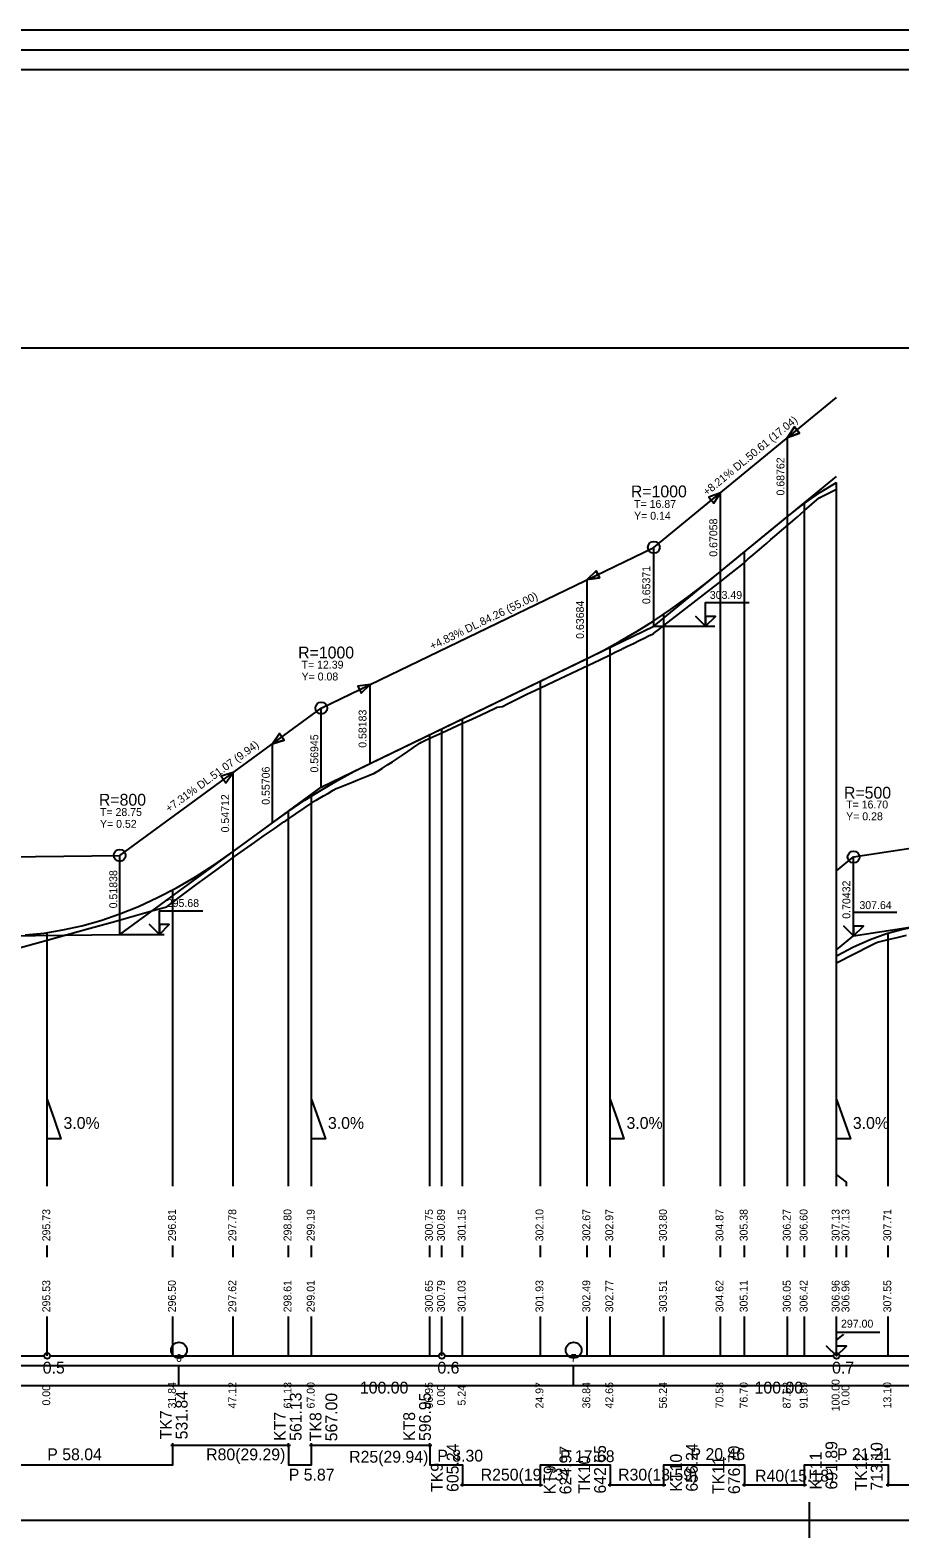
# Model space of a CAD drawing. Extents: x 999 to 1126, y 126 to 164.
# Drawn here: x 1063.75 to 1085.78, y 125.66 to 163.87 of the extents above; entities that cross this region are included whole.
import ezdxf

# ---------------------------------------------------------------- set-up
doc = ezdxf.new("R2010")
doc.units = 0
for name, color, linetype in [('KOTA', 7, 'Continuous'), ('NOVY_STAV', 7, 'Continuous'), ('NS_OBLOUK', 7, 'Continuous'), ('REZY_PO', 7, 'Continuous'), ('SESTAVY_REZU_PO', 7, 'Continuous'), ('SKLONOVE_POMERY', 7, 'Continuous'), ('SMEROVE_POMERY', 7, 'Continuous'), ('SMEROVE_POMERY_KOD', 7, 'Continuous'), ('SVK', 7, 'Continuous'), ('SVK_STAT', 7, 'Continuous'), ('TABULKY', 7, 'Continuous'), ('u_pricne_rezy', 7, 'Continuous'), ('x_formát_rám', 7, 'Continuous')]:
    doc.layers.add(name, color=color, linetype=linetype)

msp = doc.modelspace()

# ---------------------------------------------------------------- linework, layer by layer
at = {"layer": 'KOTA'}
for p, q in [((1079.549, 148.762), (1081.091, 148.762)), ((1066.016, 140.955), (1067.141, 140.955))]:
    msp.add_line(p, q, dxfattribs=at)
for points in [[(1080.861, 148.762), (1080.611, 149.012), (1080.861, 148.762), (1080.861, 149.362), (1081.961, 149.362)], [(1080.861, 149.012), (1080.861, 148.762), (1081.111, 149.012), (1080.861, 149.012)], [(1080.861, 148.762), (1081.111, 149.012), (1080.861, 149.012)], [(1080.861, 148.762), (1080.861, 148.762)], [(1067.02, 140.955), (1066.77, 141.205), (1067.02, 140.955), (1067.02, 141.555), (1068.12, 141.555)], [(1084.61, 140.916), (1084.36, 141.166), (1084.61, 140.916), (1084.61, 141.516), (1085.71, 141.516)], [(1067.02, 141.205), (1067.02, 140.955), (1067.27, 141.205), (1067.02, 141.205)], [(1067.02, 140.955), (1067.27, 141.205), (1067.02, 141.205)], [(1084.61, 141.166), (1084.61, 140.916), (1084.86, 141.166), (1084.61, 141.166)], [(1084.61, 140.916), (1084.86, 141.166), (1084.61, 141.166)], [(1067.02, 140.955), (1067.02, 140.955)], [(1084.61, 140.916), (1084.61, 140.916)], [(1084.178, 130.273), (1083.928, 130.523), (1084.178, 130.273), (1084.178, 130.873), (1085.278, 130.873)], [(1084.178, 130.273), (1084.428, 130.523), (1084.178, 130.523)]]:
    msp.add_lwpolyline(points, dxfattribs=at)
at = {"layer": 'NOVY_STAV'}
for points in [[(1079.549, 150.762), (1084.178, 154.561)], [(1054.178, 140.22), (1055.344, 140.824), (1066.016, 140.955), (1071.123, 144.689), (1079.549, 148.762), (1084.178, 152.561)], [(1063.62, 140.94), (1064.099, 140.989), (1064.578, 141.067), (1065.057, 141.173), (1065.536, 141.308), (1066.016, 141.472), (1066.495, 141.664), (1066.974, 141.885), (1067.453, 142.135), (1067.932, 142.414), (1068.411, 142.721), (1068.89, 143.057), (1069.884, 143.784), (1070.297, 144.077), (1070.71, 144.353), (1071.123, 144.612), (1071.536, 144.854), (1071.948, 145.08), (1072.361, 145.288), (1077.862, 147.946), (1078.283, 148.159), (1078.705, 148.39), (1079.127, 148.638), (1079.549, 148.904), (1079.971, 149.188), (1080.393, 149.49), (1080.814, 149.809), (1081.236, 150.147), (1082.94, 151.545), (1083.358, 151.871), (1083.775, 152.161), (1084.178, 152.408)], [(1071.123, 146.689), (1079.549, 150.762)], [(1079.549, 148.762), (1079.549, 150.762)], [(1066.016, 142.955), (1071.123, 146.689)], [(1071.123, 144.689), (1071.123, 146.689)], [(1084.178, 140.561), (1084.61, 140.916), (1091.178, 141.92), (1100.556, 145.632)], [(1084.178, 140.408), (1084.193, 140.417), (1084.61, 140.637), (1085.027, 140.823), (1085.445, 140.974), (1085.862, 141.09), (1086.28, 141.171), (1089.356, 141.642), (1089.812, 141.718), (1090.267, 141.809), (1090.723, 141.913), (1091.178, 142.031), (1091.633, 142.163), (1092.089, 142.309), (1092.544, 142.468), (1093, 142.641), (1100.556, 145.632)], [(1084.61, 142.916), (1091.178, 143.92)], [(1055.344, 142.824), (1066.016, 142.955)], [(1066.016, 140.955), (1066.016, 142.955)], [(1084.178, 142.561), (1084.61, 142.916)], [(1084.61, 140.916), (1084.61, 142.916)]]:
    msp.add_lwpolyline(points, dxfattribs=at)
for centre in [(1079.549, 150.762), (1071.123, 146.689), (1066.016, 142.955), (1084.61, 142.916)]:
    msp.add_circle(centre, 0.15, dxfattribs=at)
at = {"layer": 'NS_OBLOUK'}
for points in [[(1082.94, 153.545), (1083.236, 153.659), (1083.109, 153.813), (1082.94, 153.545)], [(1082.94, 151.545), (1082.94, 153.545)], [(1081.068, 151.879), (1081.236, 152.147), (1080.941, 152.034), (1081.068, 151.879)], [(1081.236, 150.147), (1081.236, 152.147)], [(1077.862, 149.946), (1078.175, 149.987), (1078.088, 150.167), (1077.862, 149.946)], [(1077.862, 147.946), (1077.862, 149.946)], [(1072.135, 147.067), (1072.361, 147.288), (1072.048, 147.247), (1072.135, 147.067)], [(1072.361, 145.288), (1072.361, 147.288)], [(1069.884, 145.784), (1070.185, 145.88), (1070.067, 146.041), (1069.884, 145.784)], [(1069.884, 143.784), (1069.884, 145.784)], [(1068.707, 144.799), (1068.891, 145.057), (1068.589, 144.961), (1068.707, 144.799)], [(1068.891, 143.057), (1068.891, 145.057)]]:
    msp.add_lwpolyline(points, dxfattribs=at)
for points in [[(1082.94, 153.545), (1083.109, 153.813), (1083.236, 153.659)], [(1081.236, 152.147), (1080.941, 152.034), (1081.068, 151.879)], [(1077.862, 149.946), (1078.088, 150.167), (1078.175, 149.987)], [(1072.361, 147.288), (1072.048, 147.247), (1072.135, 147.067)], [(1069.884, 145.784), (1070.067, 146.041), (1070.185, 145.88)], [(1068.891, 145.057), (1068.589, 144.961), (1068.707, 144.799)]]:
    msp.add_lwpolyline(points, close=True, dxfattribs=at)
at = {"layer": 'REZY_PO'}
for points in [[(1063.354, 140.576), (1064.178, 140.806), (1065.178, 141.086), (1065.915, 141.292), (1066.178, 141.366), (1066.885, 141.564), (1067.178, 141.645), (1067.208, 141.654), (1067.362, 141.769), (1067.362, 141.769), (1067.362, 141.769), (1067.566, 141.921), (1067.635, 141.972), (1067.77, 142.073), (1067.974, 142.224), (1068.178, 142.375), (1068.428, 142.559), (1068.678, 142.742), (1068.928, 142.924), (1069.178, 143.104), (1069.428, 143.283), (1069.469, 143.312), (1069.678, 143.459), (1069.928, 143.633), (1070.178, 143.804), (1070.235, 143.843), (1070.291, 143.881), (1070.291, 143.881), (1070.291, 143.881), (1070.878, 144.28), (1070.878, 144.28), (1070.878, 144.28), (1070.978, 144.347), (1070.994, 144.357), (1071.078, 144.405), (1071.178, 144.463), (1071.303, 144.535), (1071.428, 144.609), (1071.5, 144.651), (1071.553, 144.672), (1071.678, 144.723), (1071.803, 144.773), (1071.928, 144.824), (1072.053, 144.875), (1072.178, 144.925), (1072.303, 144.975), (1072.404, 145.015), (1072.428, 145.025), (1072.451, 145.034), (1072.539, 145.084), (1072.553, 145.092), (1072.678, 145.17), (1072.803, 145.249), (1072.928, 145.331), (1073.053, 145.413), (1073.178, 145.497), (1073.317, 145.592), (1073.456, 145.687), (1073.595, 145.783), (1073.622, 145.802), (1073.661, 145.826), (1073.734, 145.862), (1073.873, 145.927), (1073.873, 145.927), (1073.873, 145.927), (1074.178, 146.066), (1074.702, 146.304), (1074.94, 146.412), (1075.178, 146.522), (1075.511, 146.678), (1075.58, 146.711), (1075.711, 146.726), (1075.845, 146.793), (1076.178, 146.962), (1076.351, 147.05), (1076.426, 147.086), (1076.675, 147.203), (1077.178, 147.441), (1078.178, 147.915), (1078.443, 148.04), (1078.59, 148.111), (1078.737, 148.184), (1078.767, 148.199), (1078.884, 148.254), (1079.031, 148.325), (1079.178, 148.398), (1079.303, 148.462), (1079.428, 148.526), (1079.43, 148.527), (1079.538, 148.573), (1079.553, 148.584), (1079.678, 148.682), (1079.802, 148.779), (1080.178, 149.071), (1081.178, 149.848), (1081.508, 150.105), (1081.817, 150.35), (1081.848, 150.38), (1081.848, 150.38), (1081.848, 150.38), (1081.939, 150.468), (1082.013, 150.53), (1082.178, 150.669), (1082.345, 150.81), (1082.405, 150.862), (1082.511, 150.959), (1082.664, 151.084), (1082.678, 151.096), (1082.845, 151.24), (1083.011, 151.385), (1083.178, 151.53), (1083.272, 151.612), (1083.367, 151.694), (1083.736, 152.014), (1084.178, 152.237), (1084.178, 152.237)], [(1084.178, 140.237), (1085.059, 140.681), (1085.178, 140.738), (1085.216, 140.756), (1085.488, 140.823), (1085.718, 140.879), (1085.948, 140.936)]]:
    msp.add_lwpolyline(points, dxfattribs=at)
at = {"layer": 'SESTAVY_REZU_PO'}
for points in [[(1054.253, 130.273), (1064.103, 130.273)], [(1064.253, 130.273), (1074.103, 130.273)], [(1074.253, 130.273), (1084.103, 130.273)], [(1084.253, 130.273), (1094.103, 130.273)]]:
    msp.add_lwpolyline(points, dxfattribs=at)
for centre in [(1064.178, 130.273), (1074.178, 130.273), (1084.178, 130.273)]:
    msp.add_circle(centre, 0.075, dxfattribs=at)
at = {"layer": 'SKLONOVE_POMERY'}
for points in [[(1064.178, 135.773), (1064.178, 136.773), (1064.178, 136.773), (1064.353, 136.273), (1064.528, 135.773), (1064.178, 135.773)], [(1070.878, 135.773), (1070.878, 136.773), (1070.878, 136.773), (1071.053, 136.273), (1071.228, 135.773), (1070.878, 135.773)], [(1078.443, 135.773), (1078.443, 136.773), (1078.443, 136.773), (1078.618, 136.273), (1078.793, 135.773), (1078.443, 135.773)], [(1084.178, 135.773), (1084.178, 136.773), (1084.178, 136.773), (1084.353, 136.273), (1084.528, 135.773), (1084.178, 135.773)]]:
    msp.add_lwpolyline(points, dxfattribs=at)
at = {"layer": 'SMEROVE_POMERY'}
msp.add_lwpolyline([(1061.558, 127.51), (1067.362, 127.51), (1067.362, 128.01), (1070.291, 128.01), (1070.291, 127.51), (1070.878, 127.51), (1070.878, 128.01), (1073.873, 128.01), (1073.873, 127.51), (1074.702, 127.51), (1074.702, 127.01), (1076.675, 127.01), (1076.675, 127.51), (1078.443, 127.51), (1078.443, 127.01), (1079.802, 127.01), (1079.802, 127.51), (1081.848, 127.51), (1081.848, 127.01), (1083.367, 127.01), (1083.367, 127.51), (1085.488, 127.51), (1085.488, 127.01), (1087.25, 127.01)], dxfattribs=at)
at = {"layer": 'SMEROVE_POMERY_KOD'}
for points in [[(1067.312, 128.01), (1067.412, 128.01)], [(1067.362, 127.96), (1067.362, 128.06)], [(1070.241, 128.01), (1070.341, 128.01)], [(1070.291, 127.96), (1070.291, 128.06)], [(1070.828, 128.01), (1070.928, 128.01)], [(1070.878, 127.96), (1070.878, 128.06)], [(1073.823, 128.01), (1073.923, 128.01)], [(1073.873, 127.96), (1073.873, 128.06)], [(1074.652, 127.01), (1074.752, 127.01)], [(1074.702, 126.96), (1074.702, 127.06)], [(1076.625, 127.01), (1076.725, 127.01)], [(1076.675, 126.96), (1076.675, 127.06)], [(1078.393, 127.01), (1078.493, 127.01)], [(1078.443, 126.96), (1078.443, 127.06)], [(1079.752, 127.01), (1079.852, 127.01)], [(1079.802, 126.96), (1079.802, 127.06)], [(1081.798, 127.01), (1081.898, 127.01)], [(1081.848, 126.96), (1081.848, 127.06)], [(1083.317, 127.01), (1083.417, 127.01)], [(1083.367, 126.96), (1083.367, 127.06)], [(1085.438, 127.01), (1085.538, 127.01)], [(1085.488, 126.96), (1085.488, 127.06)]]:
    msp.add_lwpolyline(points, dxfattribs=at)
at = {"layer": 'SVK'}
for points in [[(1084.178, 134.573), (1084.178, 152.408)], [(1084.178, 132.773), (1084.178, 133.073)], [(1084.178, 130.273), (1084.178, 131.273)]]:
    msp.add_lwpolyline(points, dxfattribs=at)
at = {"layer": 'SVK_STAT'}
for points in [[(1083.367, 134.573), (1083.367, 151.877)], [(1082.94, 134.573), (1082.94, 151.545)], [(1081.848, 134.573), (1081.848, 150.649)], [(1081.236, 134.573), (1081.236, 150.147)], [(1079.802, 134.573), (1079.802, 149.075)], [(1078.443, 134.573), (1078.443, 148.246)], [(1077.862, 134.573), (1077.862, 147.946)], [(1076.675, 134.573), (1076.675, 147.373)], [(1074.702, 134.573), (1074.702, 146.419)], [(1073.873, 134.573), (1073.873, 146.018)], [(1074.178, 134.573), (1074.178, 146.166)], [(1070.878, 134.573), (1070.878, 144.459)], [(1070.291, 134.573), (1070.291, 144.073)], [(1068.891, 134.573), (1068.89, 143.057)], [(1084.428, 134.573), (1084.428, 134.673), (1084.178, 134.873), (1084.178, 142.408)], [(1067.362, 134.573), (1067.362, 142.088)], [(1064.178, 134.573), (1064.178, 141.002)], [(1085.488, 134.573), (1085.488, 140.986)], [(1064.178, 132.773), (1064.178, 133.073)], [(1067.362, 132.773), (1067.362, 133.073)], [(1068.891, 132.773), (1068.891, 133.073)], [(1070.291, 132.773), (1070.291, 133.073)], [(1070.878, 132.773), (1070.878, 133.073)], [(1073.873, 132.773), (1073.873, 133.073)], [(1074.178, 132.773), (1074.178, 133.073)], [(1074.702, 132.773), (1074.702, 133.073)], [(1076.675, 132.773), (1076.675, 133.073)], [(1077.862, 132.773), (1077.862, 133.073)], [(1078.443, 132.773), (1078.443, 133.073)], [(1079.802, 132.773), (1079.802, 133.073)], [(1081.236, 132.773), (1081.236, 133.073)], [(1081.848, 132.773), (1081.848, 133.073)], [(1082.94, 132.773), (1082.94, 133.073)], [(1083.367, 132.773), (1083.367, 133.073)], [(1084.428, 132.773), (1084.428, 133.073)], [(1085.488, 132.773), (1085.488, 133.073)], [(1064.178, 130.273), (1064.178, 131.273)], [(1067.362, 130.273), (1067.362, 131.273)], [(1068.891, 130.273), (1068.891, 131.273)], [(1070.291, 130.273), (1070.291, 131.273)], [(1070.878, 130.273), (1070.878, 131.273)], [(1073.873, 130.273), (1073.873, 131.273)], [(1074.178, 130.273), (1074.178, 131.273)], [(1074.702, 130.273), (1074.702, 131.273)], [(1076.675, 130.273), (1076.675, 131.273)], [(1077.862, 130.273), (1077.862, 131.273)], [(1078.443, 130.273), (1078.443, 131.273)], [(1079.802, 130.273), (1079.802, 131.273)], [(1081.236, 130.273), (1081.236, 131.273)], [(1081.848, 130.273), (1081.848, 131.273)], [(1082.94, 130.273), (1082.94, 131.273)], [(1083.367, 130.273), (1083.367, 131.273)], [(1085.488, 130.273), (1085.488, 131.273)], [(1084.178, 130.273), (1084.178, 130.673), (1084.353, 130.818), (1084.353, 130.818)]]:
    msp.add_lwpolyline(points, dxfattribs=at)
at = {"layer": 'TABULKY'}
for points in [[(1014.178, 162.868), (1100.556, 162.868), (1100.556, 163.868), (1014.178, 163.868), (1014.178, 162.868)], [(1014.178, 163.368), (1100.556, 163.368)]]:
    msp.add_lwpolyline(points, dxfattribs=at)
at = {"layer": 'u_pricne_rezy'}
for points in [[(1017.517, 129.52), (1103.895, 129.52), (1103.895, 130.02), (1017.517, 130.02), (1017.517, 129.52)], [(1067.517, 129.52), (1067.517, 130.02)], [(1077.517, 129.52), (1077.517, 130.02)]]:
    msp.add_lwpolyline(points, dxfattribs=at)
for centre in [(1067.517, 130.42), (1077.517, 130.42)]:
    msp.add_circle(centre, 0.2, dxfattribs=at)
at = {"layer": 'x_formát_rám'}
msp.add_line((1083.491, 125.663), (1083.491, 126.563), dxfattribs=at)
msp.add_lwpolyline([(999.491, 126.113), (1125.491, 126.113), (1125.491, 155.813), (999.491, 155.813)], close=True, dxfattribs=at)

# ---------------------------------------------------------------- texts
at = {"layer": 'KOTA'}
for s, p in [('303.49', (1080.968, 149.456)), ('295.68', (1067.208, 141.649)), ('307.64', (1084.758, 141.596)), ('297.00', (1084.292, 130.99))]:
    msp.add_text(s, height=0.2, dxfattribs=at).set_placement(p)
at = {"layer": 'NOVY_STAV'}
for s, rotation, p in [('+8.21% DL.50.61 (17.04)', 39.3799, (1080.894, 152.056)), (' 0.65371', 90, (1079.459, 149.251)), ('+4.83% DL.84.26 (55.00)', 25.797, (1073.933, 148.157)), (' 0.56945', 90, (1071.047, 144.982)), ('+7.31% DL.51.07 (9.94)', 36.1691, (1067.266, 144.037)), (' 0.51838', 90, (1065.953, 141.54)), (' 0.70432', 90, (1084.527, 141.277))]:
    msp.add_text(s, height=0.2, rotation=rotation, dxfattribs=at).set_placement(p)
at = {"layer": 'NS_OBLOUK'}
for s, p in [(' 0.68762', (1082.858, 152.001)), (' 0.67058', (1081.157, 150.45)), (' 0.63684', (1077.779, 148.368)), (' 0.58183', (1072.268, 145.608)), (' 0.55706', (1069.816, 144.165)), (' 0.54712', (1068.787, 143.465))]:
    msp.add_text(s, height=0.2, rotation=90, dxfattribs=at).set_placement(p)
for s, height, p in [('R=1000', 0.3, (1078.968, 152.029)), ('T= 16.87', 0.2, (1079.049, 151.762)), ('Y= 0.14', 0.2, (1079.049, 151.462)), ('R=1000', 0.3, (1070.538, 147.947)), ('T= 12.39', 0.2, (1070.623, 147.689)), ('Y= 0.08', 0.2, (1070.623, 147.389)), ('R=800', 0.3, (1065.489, 144.216)), ('R=500', 0.3, (1084.367, 144.394)), ('T= 28.75', 0.2, (1065.516, 143.955)), ('Y= 0.28', 0.2, (1084.422, 143.846)), ('T= 16.70', 0.2, (1084.422, 144.146)), ('Y= 0.52', 0.2, (1065.516, 143.655))]:
    msp.add_text(s, height=height, dxfattribs=at).set_placement(p)
at = {"layer": 'SESTAVY_REZU_PO'}
for s, p in [('0.5', (1064.066, 129.825)), ('0.6', (1074.066, 129.825)), ('0.7', (1084.066, 129.825))]:
    msp.add_text(s, height=0.3, dxfattribs=at).set_placement(p)
at = {"layer": 'SKLONOVE_POMERY'}
for p in [(1064.592, 136.026), (1071.292, 136.026), (1078.857, 136.026), (1084.592, 136.026)]:
    msp.add_text('3.0%', height=0.3, dxfattribs=at).set_placement(p)
at = {"layer": 'SMEROVE_POMERY'}
for s, p in [('P 58.04', (1064.181, 127.629)), ('R80(29.29)', (1068.206, 127.627)), ('R25(29.94)', (1071.829, 127.567)), ('P 8.30', (1074.063, 127.595)), ('P 17.68', (1077.171, 127.581)), ('P 20.46', (1080.478, 127.635)), ('P 21.21', (1084.188, 127.635)), ('P 5.87', (1070.299, 127.114)), ('R250(19.73)', (1075.162, 127.115)), ('R30(13.59)', (1078.644, 127.115)), ('R40(15.18)', (1082.115, 127.088))]:
    msp.add_text(s, height=0.3, dxfattribs=at).set_placement(p)
at = {"layer": 'SMEROVE_POMERY_KOD'}
for s, p in [('531.84', (1067.735, 128.158)), ('561.13', (1070.623, 128.12)), ('567.00', (1071.528, 128.11)), ('596.95', (1073.9, 128.117)), ('TK7', (1067.335, 128.158)), ('KT7', (1070.223, 128.12)), ('TK8', (1071.128, 128.11)), ('KT8', (1073.5, 128.117)), ('605.24', (1074.601, 126.826)), ('642.65', (1078.335, 126.785)), ('656.24', (1080.662, 126.833)), ('691.89', (1084.199, 126.887)), ('713.10', (1085.346, 126.86)), ('624.97', (1077.46, 126.765)), ('TK10', (1077.935, 126.785)), ('KT10', (1080.262, 126.833)), ('TK11', (1081.333, 126.772)), ('676.70', (1081.733, 126.772)), ('KT11', (1083.799, 126.887)), ('TK12', (1084.946, 126.86)), ('TK9', (1074.201, 126.826)), ('KT9', (1077.06, 126.765))]:
    msp.add_text(s, height=0.3, rotation=90, dxfattribs=at).set_placement(p)
at = {"layer": 'SVK'}
for s, p in [(' 307.13', (1084.255, 133.103)), (' 306.96', (1084.255, 131.303)), ('100.00', (1084.255, 128.867))]:
    msp.add_text(s, height=0.2, rotation=90, dxfattribs=at).set_placement(p)
at = {"layer": 'SVK_STAT'}
for s, p in [(' 295.73', (1064.255, 133.103)), (' 296.81', (1067.439, 133.103)), (' 297.78', (1068.967, 133.103)), (' 298.80', (1070.368, 133.103)), (' 299.19', (1070.955, 133.103)), (' 300.75', (1073.949, 133.103)), (' 300.89', (1074.255, 133.103)), (' 301.15', (1074.779, 133.103)), (' 302.10', (1076.751, 133.103)), (' 302.67', (1077.938, 133.103)), (' 302.97', (1078.52, 133.103)), (' 303.80', (1079.879, 133.103)), (' 304.87', (1081.313, 133.103)), (' 305.38', (1081.925, 133.103)), (' 306.27', (1083.017, 133.103)), (' 306.60', (1083.443, 133.103)), (' 307.13', (1084.505, 133.103)), (' 307.71', (1085.564, 133.103)), (' 295.53', (1064.255, 131.303)), (' 296.50', (1067.439, 131.303)), (' 297.62', (1068.967, 131.303)), (' 298.61', (1070.368, 131.303)), (' 299.01', (1070.955, 131.303)), (' 300.65', (1073.949, 131.303)), (' 300.79', (1074.255, 131.303)), (' 301.03', (1074.779, 131.303)), (' 301.93', (1076.751, 131.303)), (' 302.49', (1077.938, 131.303)), (' 302.77', (1078.52, 131.303)), (' 303.51', (1079.879, 131.303)), (' 304.62', (1081.313, 131.303)), (' 305.11', (1081.925, 131.303)), (' 306.05', (1083.017, 131.303)), (' 306.42', (1083.443, 131.303)), (' 306.96', (1084.505, 131.303)), (' 307.55', (1085.564, 131.303)), ('  0.00', (1064.255, 128.867)), (' 31.84', (1067.439, 128.867)), (' 47.12', (1068.967, 128.867)), (' 61.13', (1070.368, 128.867)), (' 67.00', (1070.955, 128.867)), (' 96.95', (1073.949, 128.867)), ('  0.00', (1074.255, 128.867)), ('  5.24', (1074.779, 128.867)), (' 24.97', (1076.751, 128.867)), (' 36.84', (1077.938, 128.867)), (' 42.65', (1078.52, 128.867)), (' 56.24', (1079.879, 128.867)), (' 70.58', (1081.313, 128.867)), (' 76.70', (1081.925, 128.867)), (' 87.62', (1083.017, 128.867)), (' 91.89', (1083.443, 128.867)), ('  0.00', (1084.505, 128.867)), (' 13.10', (1085.564, 128.867))]:
    msp.add_text(s, height=0.2, rotation=90, dxfattribs=at).set_placement(p)
at = {"layer": 'u_pricne_rezy'}
for s, height, p in [('6', 0.2, (1067.442, 130.12)), ('7', 0.2, (1077.442, 130.12)), ('100.00', 0.3, (1072.102, 129.32)), ('100.00', 0.3, (1082.102, 129.32))]:
    msp.add_text(s, height=height, dxfattribs=at).set_placement(p)

doc.saveas('drawing.dxf')
